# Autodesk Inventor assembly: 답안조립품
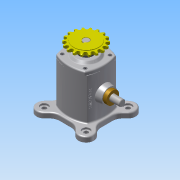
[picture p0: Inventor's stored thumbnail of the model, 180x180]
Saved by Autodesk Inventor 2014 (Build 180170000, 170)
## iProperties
Created: 2016-05
Part Number: 답안조립품
Document SubType Name: Assembly
Designer: 703-04
Author: 703-04
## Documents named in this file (11)
- C:\Users\703-04\Desktop\460508V1013\답안조립품.iam
- C:\Users\703-04\Desktop\460508V1013\본체.ipt
- C:\Users\703-04\Desktop\460508V1013\편심축.ipt
- C:\Users\703-04\Desktop\460508V1013\키5x5.ipt
- C:\Users\703-04\Desktop\460508V1013\베어링-6203.ipt
- C:\Users\703-04\Desktop\460508V1013\커버.ipt
- C:\Users\703-04\Desktop\460508V1013\오일실.ipt
- C:\Users\703-04\Desktop\460508V1013\M4x0.7x12.ipt
- C:\Users\703-04\Desktop\460508V1013\스프로킷.ipt
- C:\Users\703-04\Desktop\460508V1013\슬라이더.ipt
- C:\Users\703-04\Desktop\460508V1013\부시.ipt
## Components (8 placed, 1 different names)
1. M4x0.7x12:2
2. M4x0.7x12:3
3. M4x0.7x12:4
4. M4x0.7x12:5
5. M4x0.7x12:1
6. M4x0.7x12:6
7. M4x0.7x12:7
8. M4x0.7x12:8
